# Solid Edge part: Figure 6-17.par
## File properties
Author: TIET
Template: Iso Metric Part.par
Last saved by: CADCIM
Revision: 3
Application: Solid Edge
Accuracy: 0.990
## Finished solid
Body 1: solid body, 3 faces, 2 edges, 0 vertices.
  Faces by surface: plane 2, cylinder 1
  Edges by curve: circle 2
Bounding box of the edges (mm): 65.246 x 27.494 x 27.494, from (-32.623, -13.7473, -13.7473) to (32.623, 13.7473, 13.7473).
Cylindrical faces by radius (mm): R13.7473 x1
Planar faces by outward normal: +x 1, -x 1
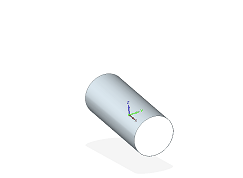
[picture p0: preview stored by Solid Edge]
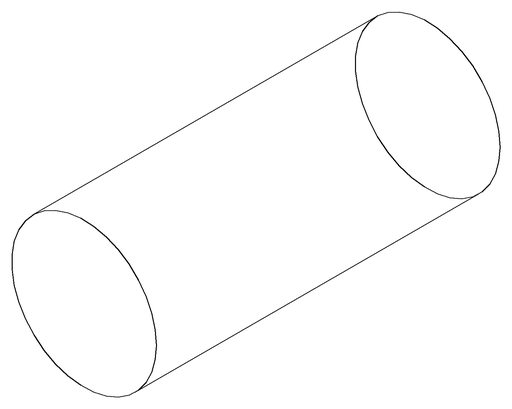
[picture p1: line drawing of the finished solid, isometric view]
